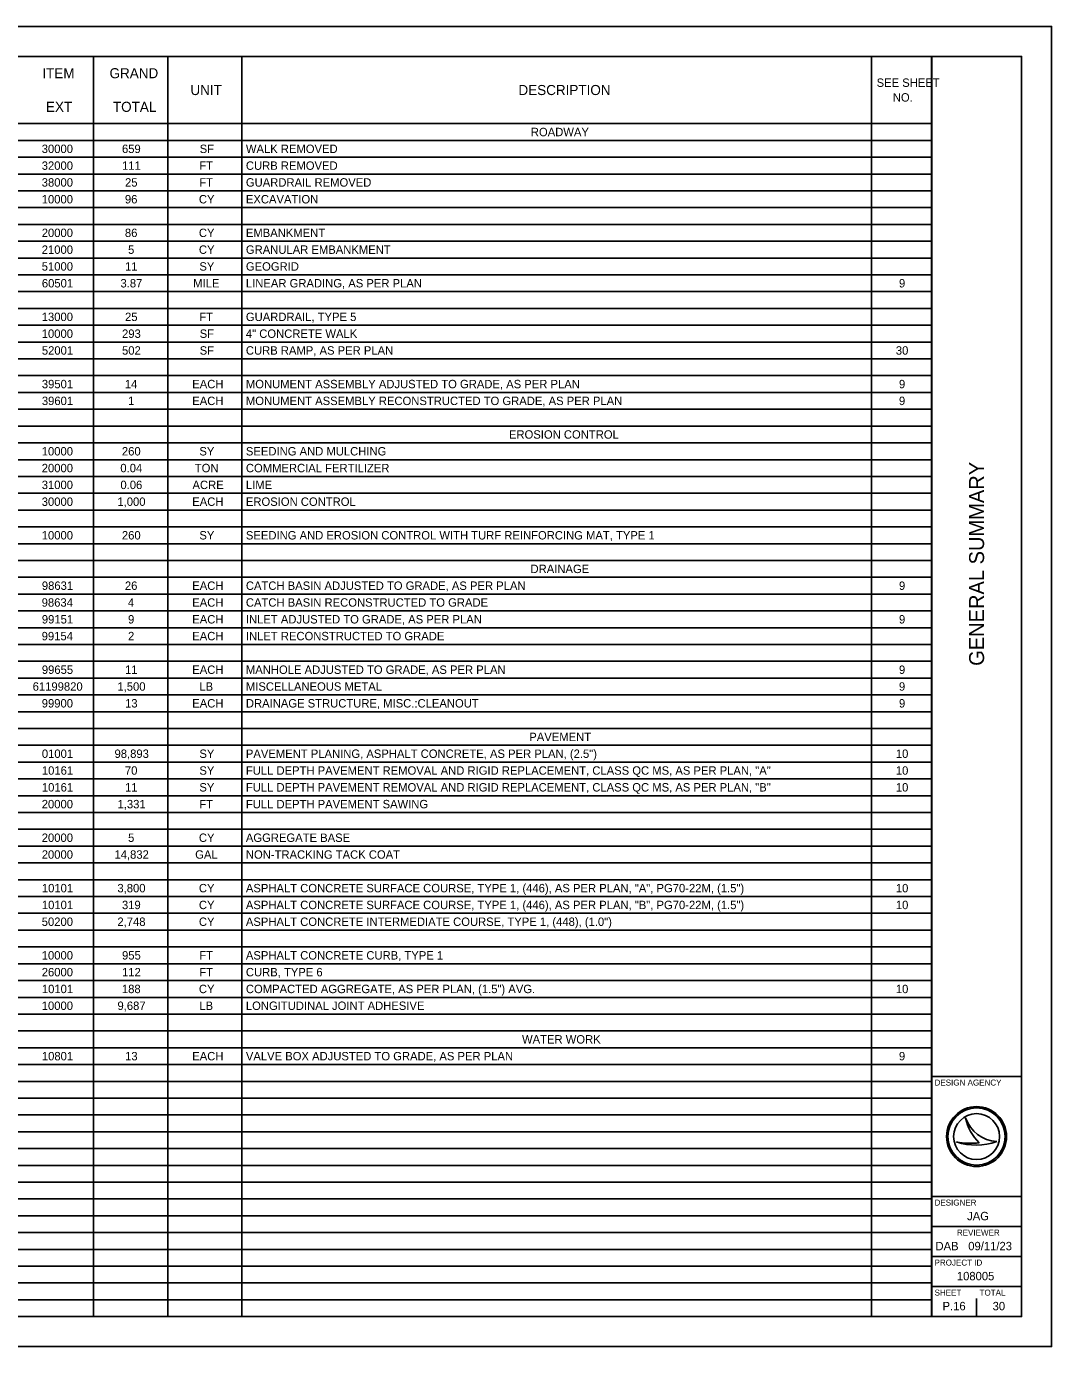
# Model space of a CAD drawing. Extents: x 0 to 34, y 0 to 22.
# Drawn here: x 16.92 to 34, y 0 to 22 of the extents above; entities that cross this region are included whole.
import ezdxf

# ---------------------------------------------------------------- set-up
doc = ezdxf.new("R2010")
doc.units = 0
for name, color, linetype in [('SH_Border', 7, 'Continuous'), ('SH_Cut_Line', 7, 'Continuous'), ('SH_Data', 7, 'Continuous'), ('SH_Text', 7, 'Continuous')]:
    doc.layers.add(name, color=color, linetype=linetype)

msp = doc.modelspace()

# ---------------------------------------------------------------- linework, layer by layer
at = {"layer": 'SH_Border'}
for p, q in [((32, 0.5), (32, 21.5)), ((32, 4.5), (33.5, 4.5)), ((32, 2.5), (33.5, 2.5)), ((32, 2), (33.5, 2)), ((32, 1.5), (33.5, 1.5)), ((32, 1), (33.5, 1))]:
    msp.add_line(p, q, dxfattribs=at)
msp.add_lwpolyline([(1.5, 21.5), (33.5, 21.5), (33.5, 0.5), (1.5, 0.5)], close=True, dxfattribs=at)
at = {"layer": 'SH_Cut_Line'}
msp.add_lwpolyline([(0, 0), (34, 0), (34, 22), (0, 22)], close=True, dxfattribs=at)
at = {"layer": 'SH_Data'}
for p, q in [((32.567, 3.81), (32.567, 3.81)), ((32.417, 3.41), (32.417, 3.41)), ((32.75, 3.5), (32.75, 3.5)), ((33.087, 3.419), (33.087, 3.419)), ((32.375, 0.675), (32.375, 0.675)), ((32.75, 0.5), (32.75, 0.8))]:
    msp.add_line(p, q, dxfattribs=at)
for radius in [0.5, 0.477, 0.477, 0.382]:
    msp.add_circle((32.75, 3.5), radius, dxfattribs=at)
for centre, radius, start, end in [((33.116, 3.998), 0.58, 198.9257, 198.9319), ((33.347, 3.97), 0.796, 191.6379, 191.6421), ((33.116, 3.998), 0.58, 198.9319, 267.1657), ((33.347, 3.97), 0.796, 191.6421, 226.0947), ((32.739, 4.37), 1.013, 251.4576, 290.0832), ((32.648, 4.654), 1.266, 259.4964, 259.4995), ((32.739, 4.37), 1.013, 251.4527, 251.4576), ((32.648, 4.654), 1.266, 259.4995, 276.6672)]:
    msp.add_arc(centre, radius, start, end, dxfattribs=at)
at = {"layer": 'SH_Text'}
for p, q in [((1.5, 21.5), (32.004, 21.5)), ((18.036, 21.5), (18.036, 0.5)), ((19.272, 21.5), (19.272, 0.5)), ((20.507, 21.5), (20.507, 0.5)), ((30.999, 21.5), (30.999, 0.5)), ((32.004, 21.5), (32.004, 0.5)), ((1.5, 20.38), (32.004, 20.38)), ((1.5, 20.1), (32.004, 20.1)), ((1.5, 19.82), (32.004, 19.82)), ((1.5, 19.54), (32.004, 19.54)), ((1.5, 19.26), (32.004, 19.26)), ((1.5, 18.98), (32.004, 18.98)), ((1.5, 18.7), (32.004, 18.7)), ((1.5, 18.42), (32.004, 18.42)), ((1.5, 18.14), (32.004, 18.14)), ((1.5, 17.86), (32.004, 17.86)), ((1.5, 17.58), (32.004, 17.58)), ((1.5, 17.3), (32.004, 17.3)), ((1.5, 17.02), (32.004, 17.02)), ((1.5, 16.74), (32.004, 16.74)), ((1.5, 16.46), (32.004, 16.46)), ((1.5, 16.18), (32.004, 16.18)), ((1.5, 15.9), (32.004, 15.9)), ((1.5, 15.62), (32.004, 15.62)), ((1.5, 15.34), (32.004, 15.34)), ((1.5, 15.06), (32.004, 15.06)), ((1.5, 14.78), (32.004, 14.78)), ((1.5, 14.5), (32.004, 14.5)), ((1.5, 14.22), (32.004, 14.22)), ((1.5, 13.94), (32.004, 13.94)), ((1.5, 13.66), (32.004, 13.66)), ((1.5, 13.38), (32.004, 13.38)), ((1.5, 13.1), (32.004, 13.1)), ((1.5, 12.82), (32.004, 12.82)), ((1.5, 12.54), (32.004, 12.54)), ((1.5, 12.26), (32.004, 12.26)), ((1.5, 11.98), (32.004, 11.98)), ((1.5, 11.7), (32.004, 11.7)), ((1.5, 11.42), (32.004, 11.42)), ((1.5, 11.14), (32.004, 11.14)), ((1.5, 10.86), (32.004, 10.86)), ((1.5, 10.58), (32.004, 10.58)), ((1.5, 10.3), (32.004, 10.3)), ((1.5, 10.02), (32.004, 10.02)), ((1.5, 9.74), (32.004, 9.74)), ((1.5, 9.46), (32.004, 9.46)), ((1.5, 9.18), (32.004, 9.18)), ((1.5, 8.9), (32.004, 8.9)), ((1.5, 8.62), (32.004, 8.62)), ((1.5, 8.34), (32.004, 8.34)), ((1.5, 8.06), (32.004, 8.06)), ((1.5, 7.78), (32.004, 7.78)), ((1.5, 7.5), (32.004, 7.5)), ((1.5, 7.22), (32.004, 7.22)), ((1.5, 6.94), (32.004, 6.94)), ((1.5, 6.66), (32.004, 6.66)), ((1.5, 6.38), (32.004, 6.38)), ((1.5, 6.1), (32.004, 6.1)), ((1.5, 5.82), (32.004, 5.82)), ((1.5, 5.54), (32.004, 5.54)), ((1.5, 5.26), (32.004, 5.26)), ((1.5, 4.98), (32.004, 4.98)), ((1.5, 4.7), (32.004, 4.7)), ((1.5, 4.42), (32.004, 4.42)), ((1.5, 4.14), (32.004, 4.14)), ((1.5, 3.86), (32.004, 3.86)), ((1.5, 3.58), (32.004, 3.58)), ((1.5, 3.3), (32.004, 3.3)), ((1.5, 3.02), (32.004, 3.02)), ((1.5, 2.74), (32.004, 2.74)), ((1.5, 2.46), (32.004, 2.46)), ((1.5, 2.18), (32.004, 2.18)), ((1.5, 1.9), (32.004, 1.9)), ((1.5, 1.62), (32.004, 1.62)), ((1.5, 1.34), (32.004, 1.34)), ((1.5, 1.06), (32.004, 1.06)), ((1.5, 0.78), (32.004, 0.78)), ((1.5, 0.5), (32.004, 0.5))]:
    msp.add_line(p, q, dxfattribs=at)

# ---------------------------------------------------------------- texts
at = {"layer": 'SH_Data'}
msp.add_text('GENERAL SUMMARY', height=0.25, rotation=90, dxfattribs=at).set_placement((32.875, 11.344))
for s, height, p in [('DESIGN AGENCY', 0.1, (32.05, 4.35)), ('DESIGNER', 0.1, (32.05, 2.35)), ('JAG', 0.14, (32.592, 2.105)), ('REVIEWER', 0.1, (32.422, 1.85)), ('DAB', 0.14, (32.065, 1.605)), ('09/11/23', 0.14, (32.611, 1.605)), ('PROJECT ID', 0.1, (32.05, 1.35)), ('108005', 0.14, (32.421, 1.105)), ('SHEET', 0.1, (32.05, 0.85)), ('TOTAL', 0.1, (32.8, 0.85)), ('P.16', 0.14, (32.183, 0.605)), ('30', 0.14, (33.017, 0.605))]:
    msp.add_text(s, height=height, dxfattribs=at).set_placement(p)
at = {"layer": 'SH_Text'}
for s, height, p in [('ITEM', 0.168, (17.181, 21.136)), ('GRAND', 0.168, (18.301, 21.136)), ('SEE SHEET ', 0.14, (31.084, 20.992)), ('UNIT', 0.168, (19.649, 20.856)), ('DESCRIPTION', 0.168, (25.115, 20.856)), ('EXT', 0.168, (17.242, 20.576)), ('TOTAL', 0.168, (18.357, 20.576)), ('NO.', 0.14, (31.354, 20.747)), ('ROADWAY', 0.14, (25.322, 20.17)), ('30000', 0.14, (17.171, 19.89)), ('659', 0.14, (18.508, 19.89)), ('SF', 0.14, (19.803, 19.89)), ('WALK REMOVED', 0.14, (20.573, 19.89)), ('32000', 0.14, (17.171, 19.61)), ('111', 0.14, (18.509, 19.61)), ('FT', 0.14, (19.796, 19.61)), ('CURB REMOVED', 0.14, (20.573, 19.61)), ('38000', 0.14, (17.171, 19.33)), ('25', 0.14, (18.559, 19.33)), ('FT', 0.14, (19.796, 19.33)), ('GUARDRAIL REMOVED', 0.14, (20.573, 19.33)), ('10000', 0.14, (17.171, 19.05)), ('96', 0.14, (18.557, 19.05)), ('CY', 0.14, (19.79, 19.05)), ('EXCAVATION', 0.14, (20.573, 19.05)), ('20000', 0.14, (17.171, 18.49)), ('86', 0.14, (18.557, 18.49)), ('CY', 0.14, (19.79, 18.49)), ('EMBANKMENT', 0.14, (20.573, 18.49)), ('21000', 0.14, (17.171, 18.21)), ('5', 0.14, (18.61, 18.21)), ('CY', 0.14, (19.79, 18.21)), ('GRANULAR EMBANKMENT', 0.14, (20.573, 18.21)), ('51000', 0.14, (17.171, 17.93)), ('11', 0.14, (18.559, 17.93)), ('SY', 0.14, (19.798, 17.93)), ('GEOGRID', 0.14, (20.573, 17.93)), ('60501', 0.14, (17.173, 17.65)), ('3.87', 0.14, (18.483, 17.65)), ('MILE', 0.14, (19.695, 17.65)), ('LINEAR GRADING, AS PER PLAN', 0.14, (20.573, 17.65)), ('9', 0.14, (31.456, 17.65)), ('13000', 0.14, (17.171, 17.09)), ('25', 0.14, (18.559, 17.09)), ('FT', 0.14, (19.796, 17.09)), ('GUARDRAIL, TYPE 5', 0.14, (20.573, 17.09)), ('10000', 0.14, (17.171, 16.81)), ('293', 0.14, (18.509, 16.81)), ('SF', 0.14, (19.803, 16.81)), ('4" CONCRETE WALK', 0.14, (20.573, 16.81)), ('52001', 0.14, (17.173, 16.53)), ('502', 0.14, (18.509, 16.53)), ('SF', 0.14, (19.803, 16.53)), ('CURB RAMP, AS PER PLAN', 0.14, (20.573, 16.53)), ('30', 0.14, (31.404, 16.53)), ('39501', 0.14, (17.173, 15.97)), ('14', 0.14, (18.556, 15.97)), ('EACH', 0.14, (19.679, 15.97)), ('MONUMENT ASSEMBLY ADJUSTED TO GRADE, AS PER PLAN', 0.14, (20.573, 15.97)), ('9', 0.14, (31.456, 15.97)), ('39601', 0.14, (17.173, 15.69)), ('1', 0.14, (18.609, 15.69)), ('EACH', 0.14, (19.679, 15.69)), ('MONUMENT ASSEMBLY RECONSTRUCTED TO GRADE, AS PER PLAN', 0.14, (20.573, 15.69)), ('9', 0.14, (31.456, 15.69)), ('EROSION CONTROL', 0.14, (24.957, 15.13)), ('10000', 0.14, (17.171, 14.85)), ('260', 0.14, (18.507, 14.85)), ('SY', 0.14, (19.798, 14.85)), ('SEEDING AND MULCHING', 0.14, (20.573, 14.85)), ('20000', 0.14, (17.171, 14.57)), ('0.04', 0.14, (18.481, 14.57)), ('TON', 0.14, (19.722, 14.57)), ('COMMERCIAL FERTILIZER', 0.14, (20.573, 14.57)), ('31000', 0.14, (17.171, 14.29)), ('0.06', 0.14, (18.482, 14.29)), ('ACRE', 0.14, (19.683, 14.29)), ('LIME', 0.14, (20.573, 14.29)), ('30000', 0.14, (17.171, 14.01)), ('1,000', 0.14, (18.432, 14.01)), ('EACH', 0.14, (19.679, 14.01)), ('EROSION CONTROL', 0.14, (20.573, 14.01)), ('10000', 0.14, (17.171, 13.45)), ('260', 0.14, (18.507, 13.45)), ('SY', 0.14, (19.798, 13.45)), ('SEEDING AND EROSION CONTROL WITH TURF REINFORCING MAT, TYPE 1', 0.14, (20.573, 13.45)), ('DRAINAGE', 0.14, (25.316, 12.89)), ('98631', 0.14, (17.173, 12.61)), ('26', 0.14, (18.557, 12.61)), ('EACH', 0.14, (19.679, 12.61)), ('CATCH BASIN ADJUSTED TO GRADE, AS PER PLAN', 0.14, (20.573, 12.61)), ('9', 0.14, (31.456, 12.61)), ('98634', 0.14, (17.17, 12.33)), ('4', 0.14, (18.607, 12.33)), ('EACH', 0.14, (19.679, 12.33)), ('CATCH BASIN RECONSTRUCTED TO GRADE', 0.14, (20.573, 12.33)), ('99151', 0.14, (17.173, 12.05)), ('9', 0.14, (18.609, 12.05)), ('EACH', 0.14, (19.679, 12.05)), ('INLET ADJUSTED TO GRADE, AS PER PLAN', 0.14, (20.573, 12.05)), ('9', 0.14, (31.456, 12.05)), ('99154', 0.14, (17.17, 11.77)), ('2', 0.14, (18.609, 11.77)), ('EACH', 0.14, (19.679, 11.77)), ('INLET RECONSTRUCTED TO GRADE', 0.14, (20.573, 11.77)), ('99655', 0.14, (17.173, 11.21)), ('11', 0.14, (18.559, 11.21)), ('EACH', 0.14, (19.679, 11.21)), ('MANHOLE ADJUSTED TO GRADE, AS PER PLAN', 0.14, (20.573, 11.21)), ('9', 0.14, (31.456, 11.21)), ('61199820', 0.14, (17.02, 10.93)), ('1,500', 0.14, (18.432, 10.93)), ('LB', 0.14, (19.798, 10.93)), ('MISCELLANEOUS METAL', 0.14, (20.573, 10.93)), ('9', 0.14, (31.456, 10.93)), ('99900', 0.14, (17.171, 10.65)), ('13', 0.14, (18.56, 10.65)), ('EACH', 0.14, (19.679, 10.65)), ('DRAINAGE STRUCTURE, MISC.:CLEANOUT', 0.14, (20.573, 10.65)), ('9', 0.14, (31.456, 10.65)), ('PAVEMENT', 0.14, (25.296, 10.09)), ('01001', 0.14, (17.173, 9.81)), ('98,893', 0.14, (18.384, 9.81)), ('SY', 0.14, (19.798, 9.81)), ('PAVEMENT PLANING, ASPHALT CONCRETE, AS PER PLAN, (2.5")', 0.14, (20.573, 9.81)), ('10', 0.14, (31.404, 9.81)), ('10161', 0.14, (17.173, 9.53)), ('70', 0.14, (18.557, 9.53)), ('SY', 0.14, (19.798, 9.53)), ('FULL DEPTH PAVEMENT REMOVAL AND RIGID REPLACEMENT, CLASS QC MS, AS PER PLAN, "A"', 0.14, (20.573, 9.53)), ('10', 0.14, (31.404, 9.53)), ('10161', 0.14, (17.173, 9.25)), ('11', 0.14, (18.559, 9.25)), ('SY', 0.14, (19.798, 9.25)), ('FULL DEPTH PAVEMENT REMOVAL AND RIGID REPLACEMENT, CLASS QC MS, AS PER PLAN, "B"', 0.14, (20.573, 9.25)), ('10', 0.14, (31.404, 9.25)), ('20000', 0.14, (17.171, 8.97)), ('1,331', 0.14, (18.434, 8.97)), ('FT', 0.14, (19.796, 8.97)), ('FULL DEPTH PAVEMENT SAWING', 0.14, (20.573, 8.97)), ('20000', 0.14, (17.171, 8.41)), ('5', 0.14, (18.61, 8.41)), ('CY', 0.14, (19.79, 8.41)), ('AGGREGATE BASE', 0.14, (20.573, 8.41)), ('20000', 0.14, (17.171, 8.13)), ('14,832', 0.14, (18.383, 8.13)), ('GAL', 0.14, (19.728, 8.13)), ('NON-TRACKING TACK COAT', 0.14, (20.573, 8.13)), ('10101', 0.14, (17.173, 7.57)), ('3,800', 0.14, (18.432, 7.57)), ('CY', 0.14, (19.79, 7.57)), ('ASPHALT CONCRETE SURFACE COURSE, TYPE 1, (446), AS PER PLAN, "A", PG70-22M, (1.5")', 0.14, (20.573, 7.57)), ('10', 0.14, (31.404, 7.57)), ('10101', 0.14, (17.173, 7.29)), ('319', 0.14, (18.508, 7.29)), ('CY', 0.14, (19.79, 7.29)), ('ASPHALT CONCRETE SURFACE COURSE, TYPE 1, (446), AS PER PLAN, "B", PG70-22M, (1.5")', 0.14, (20.573, 7.29)), ('10', 0.14, (31.404, 7.29)), ('50200', 0.14, (17.171, 7.01)), ('2,748', 0.14, (18.432, 7.01)), ('CY', 0.14, (19.79, 7.01)), ('ASPHALT CONCRETE INTERMEDIATE COURSE, TYPE 1, (448), (1.0")', 0.14, (20.573, 7.01)), ('10000', 0.14, (17.171, 6.45)), ('955', 0.14, (18.509, 6.45)), ('FT', 0.14, (19.796, 6.45)), ('ASPHALT CONCRETE CURB, TYPE 1', 0.14, (20.573, 6.45)), ('26000', 0.14, (17.171, 6.17)), ('112', 0.14, (18.509, 6.17)), ('FT', 0.14, (19.796, 6.17)), ('CURB, TYPE 6', 0.14, (20.573, 6.17)), ('10101', 0.14, (17.173, 5.89)), ('188', 0.14, (18.507, 5.89)), ('CY', 0.14, (19.79, 5.89)), ('COMPACTED AGGREGATE, AS PER PLAN, (1.5") AVG.', 0.14, (20.573, 5.89)), ('10', 0.14, (31.404, 5.89)), ('10000', 0.14, (17.171, 5.61)), ('9,687', 0.14, (18.433, 5.61)), ('LB', 0.14, (19.798, 5.61)), ('LONGITUDINAL JOINT ADHESIVE', 0.14, (20.573, 5.61)), ('WATER WORK', 0.14, (25.175, 5.05)), ('10801', 0.14, (17.173, 4.77)), ('13', 0.14, (18.56, 4.77)), ('EACH', 0.14, (19.679, 4.77)), ('VALVE BOX ADJUSTED TO GRADE, AS PER PLAN', 0.14, (20.573, 4.77)), ('9', 0.14, (31.456, 4.77))]:
    msp.add_text(s, height=height, dxfattribs=at).set_placement(p)

doc.saveas('drawing.dxf')
